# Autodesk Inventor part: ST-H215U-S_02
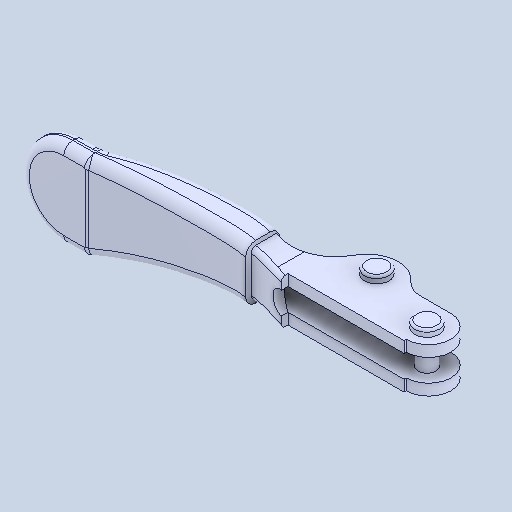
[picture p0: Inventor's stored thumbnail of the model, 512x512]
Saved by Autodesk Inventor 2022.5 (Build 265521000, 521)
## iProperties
Created: 2024-07
Part Number: ST-H215U-S_02
Material: 一般
Document SubType Name: Modeling
Designer: ImaoCorp
Density: 1 g/cm^3
Appearance: 既定
Author: ImaoCorp
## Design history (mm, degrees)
feature "ST-H215U-S_02"
node "ソリッド1"
